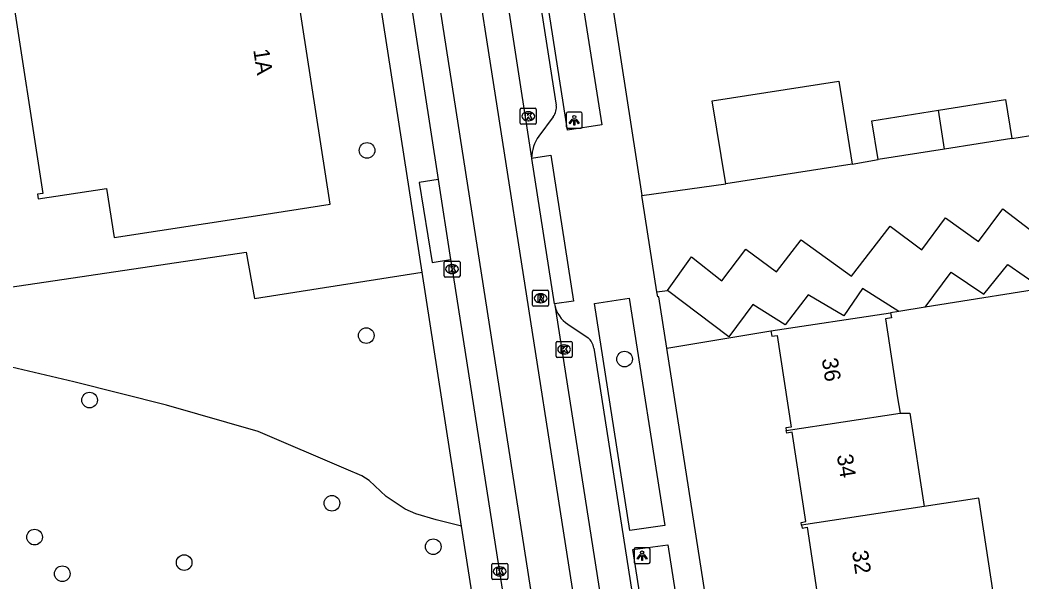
# Model space of a CAD drawing. Extents: x 160077 to 160945, y 386481 to 387498.
# Drawn here: x 160620.3 to 160683, y 387008.3 to 387043.5 of the extents above; entities that cross this region are included whole.
import ezdxf

# ---------------------------------------------------------------- set-up
doc = ezdxf.new("R2010")
doc.units = 0
for name, color, linetype in [('IMGEO_Boom', 7, 'Continuous'), ('IMGEO_Groenvoorziening', 7, 'Continuous'), ('IMGEO_Haag', 7, 'Continuous'), ('IMGEO_Kolk', 7, 'Continuous'), ('IMGEO_Lichtpunt', 7, 'Continuous'), ('IMGEO_Pand', 7, 'Continuous'), ('IMGEO_Pand_nummerreeks', 7, 'Continuous'), ('IMGEO_Parkeervlak_open', 7, 'Continuous'), ('IMGEO_Rijbaan_lokaal_gesloten', 7, 'Continuous'), ('IMGEO_Rijbaan_lokaal_open', 7, 'Continuous'), ('IMGEO_Rioolput', 7, 'Continuous'), ('IMGEO_Voetpad_open', 7, 'Continuous')]:
    doc.layers.add(name, color=color, linetype=linetype)

msp = doc.modelspace()

# ---------------------------------------------------------------- linework, layer by layer
at = {"layer": 'IMGEO_Boom'}
for centre in [(160642.011, 387035.315), (160641.965, 387023.728), (160658.123, 387022.255), (160624.65, 387019.689), (160639.817, 387013.237), (160621.214, 387011.114), (160646.155, 387010.517), (160630.571, 387009.522), (160622.946, 387008.823)]:
    msp.add_circle(centre, 0.489, dxfattribs=at)
at = {"layer": 'IMGEO_Groenvoorziening'}
for points in [[(160617.291, 387043.326), (160618.883, 387033.548), (160618.503, 387033.408), (160619.675, 387026.755), (160634.446, 387028.948), (160634.967, 387026.051), (160645.46, 387027.698)], [(160647.931, 387011.797), (160646.34, 387012.194), (160645.057, 387012.565), (160644.406, 387012.865), (160643.214, 387013.66), (160642.14, 387014.667), (160641.684, 387014.951), (160640.697, 387015.368), (160635.207, 387017.73), (160629.459, 387019.378), (160623.661, 387020.839), (160617.624, 387022.255), (160611.443, 387024.389), (160605.518, 387027.158), (160603.876, 387027.721)]]:
    msp.add_lwpolyline(points, dxfattribs=at)
at = {"layer": 'IMGEO_Haag'}
for points in [[(160685.589, 387026.885), (160676.938, 387025.506)], [(160675.292, 387025.243), (160674.763, 387025.159)], [(160660.76, 387022.948), (160667.281, 387024.014)]]:
    msp.add_lwpolyline(points, dxfattribs=at)
at = {"layer": 'IMGEO_Kolk'}
for p, q in [((160651.598, 387037.028), (160651.598, 387037.88)), ((160651.673, 387037.954), (160652.525, 387037.954)), ((160652.599, 387037.88), (160652.599, 387037.028)), ((160652.086, 387037.734), (160652.111, 387037.734)), ((160652.525, 387036.954), (160651.673, 387036.954)), ((160652.109, 387037.174), (160652.084, 387037.174)), ((160646.827, 387027.464), (160646.827, 387028.316)), ((160646.902, 387028.39), (160647.754, 387028.39)), ((160647.315, 387028.17), (160647.34, 387028.17)), ((160647.828, 387028.316), (160647.828, 387027.464)), ((160647.754, 387027.39), (160646.902, 387027.39)), ((160647.338, 387027.61), (160647.313, 387027.61)), ((160653.839, 387022.433), (160653.839, 387023.285)), ((160653.914, 387023.359), (160654.766, 387023.359)), ((160654.327, 387023.139), (160654.352, 387023.139)), ((160654.84, 387023.285), (160654.84, 387022.433)), ((160654.766, 387022.359), (160653.914, 387022.359)), ((160654.35, 387022.579), (160654.325, 387022.579)), ((160649.812, 387008.545), (160649.812, 387009.397)), ((160649.887, 387009.471), (160650.739, 387009.471)), ((160650.3, 387009.251), (160650.325, 387009.251)), ((160650.813, 387009.397), (160650.813, 387008.545)), ((160650.739, 387008.471), (160649.887, 387008.471)), ((160650.323, 387008.691), (160650.298, 387008.691))]:
    msp.add_line(p, q, dxfattribs=at)
for points in [[(160651.598, 387037.028), (160651.598, 387037.88)], [(160651.673, 387037.954), (160652.525, 387037.954)], [(160652.599, 387037.88), (160652.599, 387037.028)], [(160651.919, 387037.654), (160652.042, 387037.654), (160652.042, 387037.503), (160652.172, 387037.654), (160652.336, 387037.654), (160652.19, 387037.503), (160652.343, 387037.254), (160652.191, 387037.254), (160652.106, 387037.418), (160652.042, 387037.351), (160652.042, 387037.254), (160651.919, 387037.254), (160651.919, 387037.654)], [(160652.525, 387036.954), (160651.673, 387036.954)], [(160646.827, 387027.464), (160646.827, 387028.316)], [(160646.902, 387028.39), (160647.754, 387028.39)], [(160647.148, 387028.09), (160647.271, 387028.09), (160647.271, 387027.939), (160647.401, 387028.09), (160647.565, 387028.09), (160647.419, 387027.939), (160647.572, 387027.69), (160647.42, 387027.69), (160647.335, 387027.854), (160647.271, 387027.787), (160647.271, 387027.69), (160647.148, 387027.69), (160647.148, 387028.09)], [(160647.828, 387028.316), (160647.828, 387027.464)], [(160647.754, 387027.39), (160646.902, 387027.39)], [(160653.839, 387022.433), (160653.839, 387023.285)], [(160653.914, 387023.359), (160654.766, 387023.359)], [(160654.16, 387023.059), (160654.283, 387023.059), (160654.283, 387022.908), (160654.413, 387023.059), (160654.577, 387023.059), (160654.431, 387022.908), (160654.584, 387022.659), (160654.432, 387022.659), (160654.347, 387022.823), (160654.283, 387022.756), (160654.283, 387022.659), (160654.16, 387022.659), (160654.16, 387023.059)], [(160654.84, 387023.285), (160654.84, 387022.433)], [(160654.766, 387022.359), (160653.914, 387022.359)], [(160649.812, 387008.545), (160649.812, 387009.397)], [(160649.887, 387009.471), (160650.739, 387009.471)], [(160650.133, 387009.171), (160650.256, 387009.171), (160650.256, 387009.02), (160650.386, 387009.171), (160650.55, 387009.171), (160650.404, 387009.02), (160650.557, 387008.771), (160650.405, 387008.771), (160650.32, 387008.935), (160650.256, 387008.868), (160650.256, 387008.771), (160650.133, 387008.771), (160650.133, 387009.171)], [(160650.813, 387009.397), (160650.813, 387008.545)], [(160650.739, 387008.471), (160649.887, 387008.471)]]:
    msp.add_lwpolyline(points, dxfattribs=at)
for centre, start, end in [((160651.675, 387037.878), 91.55205, 178.44795), ((160651.675, 387037.878), 91.55205, 178.44795), ((160652.523, 387037.878), 1.55205, 88.44795), ((160652.523, 387037.878), 1.55205, 88.44795), ((160651.675, 387037.03), 181.55205, 268.44795), ((160651.675, 387037.03), 181.55205, 268.44795), ((160652.523, 387037.03), 271.55205, 358.44795), ((160652.523, 387037.03), 271.55205, 358.44795), ((160646.904, 387028.314), 91.55205, 178.44795), ((160646.904, 387028.314), 91.55205, 178.44795), ((160647.752, 387028.314), 1.55205, 88.44795), ((160647.752, 387028.314), 1.55205, 88.44795), ((160646.904, 387027.466), 181.55205, 268.44795), ((160646.904, 387027.466), 181.55205, 268.44795), ((160647.752, 387027.466), 271.55205, 358.44795), ((160647.752, 387027.466), 271.55205, 358.44795), ((160653.916, 387023.283), 91.55205, 178.44795), ((160653.916, 387023.283), 91.55205, 178.44795), ((160654.764, 387023.283), 1.55205, 88.44795), ((160654.764, 387023.283), 1.55205, 88.44795), ((160653.916, 387022.435), 181.55205, 268.44795), ((160653.916, 387022.435), 181.55205, 268.44795), ((160654.764, 387022.435), 271.55205, 358.44795), ((160654.764, 387022.435), 271.55205, 358.44795), ((160649.889, 387009.395), 91.55205, 178.44795), ((160649.889, 387009.395), 91.55205, 178.44795), ((160650.737, 387009.395), 1.55205, 88.44795), ((160650.737, 387009.395), 1.55205, 88.44795), ((160649.889, 387008.547), 181.55205, 268.44795), ((160649.889, 387008.547), 181.55205, 268.44795), ((160650.737, 387008.547), 271.55205, 358.44795), ((160650.737, 387008.547), 271.55205, 358.44795)]:
    msp.add_arc(centre, 0.0765, start, end, dxfattribs=at)
for centre, major_axis, ratio, start_param, end_param in [((160652.085, 387037.454), (-0.387, 0.002), 0.722429, 4.712389, 7.853982), ((160652.11, 387037.454), (-0.39, 0.002), 0.717154, 1.570796, 4.712389), ((160647.314, 387027.89), (-0.387, 0.002), 0.722429, 4.712389, 7.853982), ((160647.339, 387027.89), (-0.39, 0.002), 0.717154, 1.570796, 4.712389), ((160654.326, 387022.859), (-0.387, 0.002), 0.722429, 4.712389, 7.853982), ((160654.351, 387022.859), (-0.39, 0.002), 0.717154, 1.570796, 4.712389), ((160650.299, 387008.971), (-0.387, 0.002), 0.722429, 4.712389, 7.853982), ((160650.324, 387008.971), (-0.39, 0.002), 0.717154, 1.570796, 4.712389)]:
    msp.add_ellipse(centre, major_axis=major_axis, ratio=ratio, start_param=start_param, end_param=end_param, dxfattribs=at)
at = {"layer": 'IMGEO_Lichtpunt'}
for p, q in [((160654.479, 387037.61), (160654.479, 387036.803)), ((160654.479, 387037.61), (160654.479, 387036.803)), ((160655.381, 387037.705), (160654.573, 387037.705)), ((160655.381, 387037.705), (160654.573, 387037.705)), ((160655.475, 387036.803), (160655.475, 387037.61)), ((160655.475, 387036.803), (160655.475, 387037.61)), ((160654.573, 387036.709), (160655.381, 387036.709)), ((160654.573, 387036.709), (160655.381, 387036.709)), ((160658.722, 387010.356), (160658.722, 387009.549)), ((160658.722, 387010.356), (160658.722, 387009.549)), ((160659.624, 387010.451), (160658.816, 387010.451)), ((160659.624, 387010.451), (160658.816, 387010.451)), ((160659.718, 387009.549), (160659.718, 387010.356)), ((160659.718, 387009.549), (160659.718, 387010.356)), ((160658.816, 387009.455), (160659.624, 387009.455)), ((160658.816, 387009.455), (160659.624, 387009.455))]:
    msp.add_line(p, q, dxfattribs=at)
for points in [[(160654.853, 387037.274), (160654.892, 387037.246), (160654.704, 387036.984), (160654.666, 387037.011), (160654.853, 387037.274)], [(160654.955, 387037.226), (160655.002, 387037.226), (160655.002, 387036.904), (160654.955, 387036.904), (160654.955, 387037.226)], [(160655.065, 387037.246), (160655.103, 387037.273), (160655.29, 387037.011), (160655.251, 387036.983), (160655.065, 387037.246)], [(160659.096, 387010.02), (160659.135, 387009.992), (160658.947, 387009.73), (160658.909, 387009.757), (160659.096, 387010.02)], [(160659.198, 387009.972), (160659.245, 387009.972), (160659.245, 387009.65), (160659.198, 387009.65), (160659.198, 387009.972)], [(160659.308, 387009.992), (160659.346, 387010.019), (160659.533, 387009.757), (160659.494, 387009.729), (160659.308, 387009.992)]]:
    msp.add_lwpolyline(points, dxfattribs=at)
for centre in [(160654.978, 387037.408), (160659.221, 387010.154)]:
    msp.add_circle(centre, 0.0994, dxfattribs=at)
for centre, start, end in [((160654.573, 387037.61), 90, 180), ((160654.573, 387037.61), 90, 180), ((160655.381, 387037.61), 0, 90), ((160655.381, 387037.61), 0, 90), ((160654.573, 387036.803), 180, 270), ((160654.573, 387036.803), 180, 270), ((160655.381, 387036.803), 270, 0), ((160655.381, 387036.803), 270, 360), ((160658.816, 387010.356), 90, 180), ((160658.816, 387010.356), 90, 180), ((160659.624, 387010.356), 0, 90), ((160659.624, 387010.356), 0, 90), ((160658.816, 387009.549), 180, 270), ((160658.816, 387009.549), 180, 270), ((160659.624, 387009.549), 270, 0), ((160659.624, 387009.549), 270, 360)]:
    msp.add_arc(centre, 0.0946, start, end, dxfattribs=at)
at = {"layer": 'IMGEO_Pand'}
for points in [[(160618.448, 387050.94), (160618.493, 387050.651), (160618.933, 387050.719), (160619.697, 387045.778), (160621.731, 387032.627), (160621.399, 387032.576), (160621.445, 387032.278), (160625.718, 387032.939), (160626.194, 387029.858), (160634.759, 387031.183), (160639.7, 387031.947), (160636.777, 387050.85), (160626.533, 387049.266), (160626.091, 387052.122)], [(160664.449, 387033.226), (160663.614, 387038.417), (160671.521, 387039.638), (160672.355, 387034.452)], [(160677.766, 387037.832), (160681.961, 387038.495), (160682.346, 387036.059)], [(160673.985, 387034.737), (160673.6, 387037.173), (160677.766, 387037.832)], [(160678.148, 387035.395), (160677.766, 387037.832)], [(160682.346, 387036.059), (160678.148, 387035.395)], [(160678.148, 387035.395), (160673.985, 387034.737)], [(160672.355, 387034.452), (160664.449, 387033.226)], [(160667.281, 387024.014), (160674.763, 387025.159)], [(160674.763, 387025.159), (160674.814, 387024.828), (160674.453, 387024.773), (160675.209, 387019.831), (160675.356, 387018.871)], [(160667.281, 387024.014), (160667.33, 387023.69), (160667.674, 387023.742), (160668.553, 387018), (160668.218, 387017.948), (160668.243, 387017.785)], [(160668.243, 387017.785), (160675.356, 387018.871)], [(160675.356, 387018.871), (160675.969, 387018.878), (160676.864, 387013.031)], [(160669.199, 387011.86), (160669.172, 387012.038), (160669.465, 387012.083), (160668.609, 387017.673), (160668.268, 387017.621), (160668.243, 387017.785)], [(160677.787, 387007.005), (160681.21, 387007.528), (160680.287, 387013.554), (160676.864, 387013.031)], [(160676.864, 387013.031), (160669.199, 387011.86)], [(160669.199, 387011.86), (160669.227, 387011.68), (160669.538, 387011.728), (160670.407, 387006.048), (160670.016, 387005.988), (160670.058, 387005.825)]]:
    msp.add_lwpolyline(points, dxfattribs=at)
at = {"layer": 'IMGEO_Parkeervlak_open'}
for points in [[(160676.938, 387025.506), (160678.559, 387027.689), (160680.604, 387026.323), (160682.094, 387028.18), (160684.135, 387026.765), (160685.648, 387028.67), (160683.827, 387030.102)], [(160675.292, 387025.243), (160673.001, 387026.666), (160671.848, 387024.966), (160669.61, 387026.28), (160668.162, 387024.397), (160666.141, 387025.678), (160664.642, 387023.653), (160660.806, 387026.551)], [(160676.938, 387025.506), (160675.292, 387025.243)]]:
    msp.add_lwpolyline(points, dxfattribs=at)
at = {"layer": 'IMGEO_Rijbaan_lokaal_gesloten'}
for points in [[(160648.402, 387049.206), (160672.534, 386894.617)], [(160650.039, 387049.469), (160652.31, 387034.83)], [(160644.138, 387048.521), (160646.46, 387033.502)], [(160645.848, 387048.796), (160669.948, 386894.233)], [(160653.742, 387025.709), (160652.315, 387034.8), (160652.31, 387034.83)], [(160646.46, 387033.502), (160647.235, 387028.489)], [(160647.235, 387028.489), (160647.328, 387027.89), (160662.549, 386930.569), (160663.045, 386927.404)], [(160653.742, 387025.709), (160653.752, 387025.629)], [(160653.752, 387025.629), (160670.124, 386921.003), (160671.293, 386913.55)]]:
    msp.add_lwpolyline(points, dxfattribs=at)
at = {"layer": 'IMGEO_Rijbaan_lokaal_open'}
for points in [[(160682.346, 387036.059), (160686.001, 387036.637)], [(160672.355, 387034.452), (160673.985, 387034.737)], [(160659.21, 387032.487), (160664.449, 387033.226)], [(160660.147, 387026.474), (160659.271, 387032.093), (160659.21, 387032.487)], [(160660.806, 387026.551), (160662.301, 387028.657), (160664.218, 387027.153), (160665.706, 387029.132), (160667.635, 387027.709), (160669.18, 387029.729), (160672.311, 387027.453), (160674.734, 387030.579), (160676.729, 387029.09), (160678.207, 387031.094), (160680.267, 387029.624), (160681.792, 387031.664), (160683.827, 387030.102)], [(160660.147, 387026.474), (160660.806, 387026.551)]]:
    msp.add_lwpolyline(points, dxfattribs=at)
at = {"layer": 'IMGEO_Rioolput'}
for p, q in [((160652.445, 387026.56), (160653.297, 387026.56)), ((160652.37, 387025.634), (160652.37, 387026.486)), ((160652.858, 387026.34), (160652.883, 387026.34)), ((160653.371, 387026.486), (160653.371, 387025.634)), ((160653.297, 387025.56), (160652.445, 387025.56)), ((160652.881, 387025.78), (160652.856, 387025.78))]:
    msp.add_line(p, q, dxfattribs=at)
for points in [[(160652.445, 387026.56), (160653.297, 387026.56)], [(160652.37, 387025.634), (160652.37, 387026.486)], [(160652.959, 387026.258), (160652.707, 387026.26), (160652.707, 387025.86)], [(160652.707, 387025.86), (160652.831, 387025.86), (160652.831, 387026.022), (160652.842, 387026.022)], [(160652.885, 387026.179), (160652.831, 387026.179), (160652.831, 387026.098)], [(160652.831, 387026.098), (160652.883, 387026.098)], [(160652.889, 387025.993), (160652.96, 387025.86), (160653.1, 387025.86), (160653.035, 387025.986)], [(160653.371, 387026.486), (160653.371, 387025.634)], [(160653.297, 387025.56), (160652.445, 387025.56)]]:
    msp.add_lwpolyline(points, dxfattribs=at)
for centre, radius, start, end in [((160652.447, 387026.484), 0.0765, 91.55205, 178.44795), ((160652.447, 387026.484), 0.0765, 91.55205, 178.44795), ((160653.295, 387026.484), 0.0765, 1.55205, 88.44795), ((160653.295, 387026.484), 0.0765, 1.55205, 88.44795), ((160652.841, 387025.969), 0.0533, 26.02933, 88.69889), ((160652.867, 387026.287), 0.19, 274.7715, 282.96867), ((160652.891, 387026.083), 0.0964, 77.00612, 93.18647), ((160652.905, 387026.14), 0.0378, 276.66336, 79.67722), ((160652.958, 387026.148), 0.109, 350.36119, 89.41601), ((160652.956, 387026.148), 0.112, 277.58423, 350.98172), ((160652.94, 387025.933), 0.108, 29.51342, 73.79051), ((160652.447, 387025.636), 0.0765, 181.55205, 268.44795), ((160652.447, 387025.636), 0.0765, 181.55205, 268.44795), ((160653.295, 387025.636), 0.0765, 271.55205, 358.44795), ((160653.295, 387025.636), 0.0765, 271.55205, 358.44795)]:
    msp.add_arc(centre, radius, start, end, dxfattribs=at)
for centre, major_axis, ratio, start_param, end_param in [((160652.857, 387026.06), (-0.387, 0.002), 0.722429, 4.712389, 7.853982), ((160652.882, 387026.06), (-0.39, 0.002), 0.717154, 1.570796, 4.712389)]:
    msp.add_ellipse(centre, major_axis=major_axis, ratio=ratio, start_param=start_param, end_param=end_param, dxfattribs=at)
at = {"layer": 'IMGEO_Voetpad_open'}
for points in [[(160655.916, 387053.83), (160659.21, 387032.487)], [(160645.46, 387027.698), (160641.577, 387052.693)], [(160654.328, 387051.989), (160656.71, 387036.92), (160654.546, 387036.579), (160652.907, 387047.182), (160652.222, 387051.6)], [(160652.33, 387047.904), (160653.85, 387038.156)], [(160653.658, 387037.423), (160652.761, 387036.213)], [(160652.31, 387034.83), (160653.515, 387035.016), (160654.928, 387025.889), (160653.742, 387025.709)], [(160646.46, 387033.502), (160645.271, 387033.31), (160646.081, 387028.302), (160647.235, 387028.489)], [(160647.931, 387011.797), (160645.46, 387027.698)], [(160656.236, 387025.743), (160658.415, 387026.07), (160660.651, 387011.833), (160658.449, 387011.536), (160656.236, 387025.743)], [(160660.76, 387022.948), (160660.261, 387026.144), (160660.197, 387026.15), (160660.147, 387026.474)], [(160654.572, 387024.436), (160655.841, 387023.592)], [(160656.203, 387022.932), (160671.24, 386926.7), (160672.81, 386916.832)], [(160677.601, 386915.063), (160660.76, 387022.948)], [(160649.771, 386999.952), (160647.931, 387011.797)], [(160658.633, 387010.346), (160660.82, 387010.632), (160663.323, 386994.587), (160661.158, 386994.226), (160658.633, 387010.346)]]:
    msp.add_lwpolyline(points, dxfattribs=at)
for centre, radius, start, end in [((160652.82, 387038.034), 1.037, 323.9026, 6.74113), ((160654.822, 387034.776), 2.513, 145.11246, 178.76497), ((160655.647, 387026.053), 1.942, 192.6141, 236.39071), ((160655.176, 387022.798), 1.036, 7.43801, 50.05019)]:
    msp.add_arc(centre, radius, start, end, dxfattribs=at)

# ---------------------------------------------------------------- texts
at = {"layer": 'IMGEO_Pand_nummerreeks'}
for s, rotation, p in [('1A', 278.79012, (160634.889, 387041.602)), ('36', 278.90304, (160670.457, 387022.261)), ('34', 278.90304, (160671.401, 387016.236)), ('32', 278.90355, (160672.345, 387010.214))]:
    msp.add_text(s, height=1, rotation=rotation, dxfattribs=at).set_placement(p)

doc.saveas('drawing.dxf')
